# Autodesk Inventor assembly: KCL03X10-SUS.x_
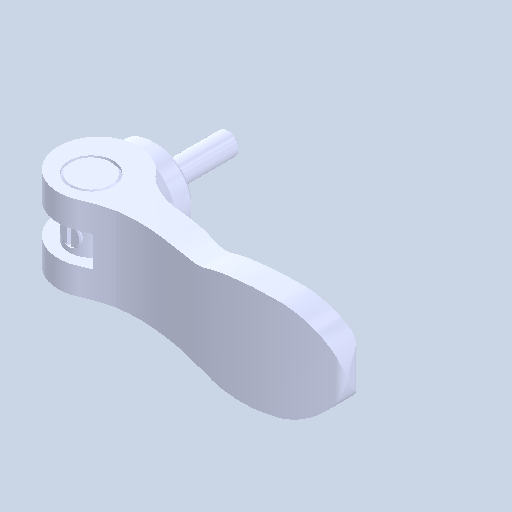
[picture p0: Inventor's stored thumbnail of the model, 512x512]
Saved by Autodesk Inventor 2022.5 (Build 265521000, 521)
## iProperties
Created: 2024-08
Part Number: KCL03X10-SUS.x_
Document SubType Name: Assembly
Designer: ImaoCorp
Author: ImaoCorp
Sending System: SOLIDWORKS 2022-2022290
MC: AMD64
MC_MODEL: Intel64 Family 6 Model 60 Stepping 3, GenuineIntel
OS: Windows_NT
FRU: Parasolid Version 33.1, build 260,  4-25-2022
FORMAT: text
GUISE: transmit
KEY: FILEKCL03X10-SUS.x_t
DATE: Thu Aug 29 10:46:44 2024
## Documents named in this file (5)
- Y:\5.更新分\2024年対応\1001_KCL\データ\kcl03x10-sus\KCL03X10-SUS.x_.iam
- Y:\5.更新分\2024年対応\1001_KCL\データ\kcl03x10-sus\KCL03X10-SUS_01.ipt
- Y:\5.更新分\2024年対応\1001_KCL\データ\kcl03x10-sus\KCL03X10-SUS_02.ipt
- Y:\5.更新分\2024年対応\1001_KCL\データ\kcl03x10-sus\KCL03X10-SUS_03.ipt
- Y:\5.更新分\2024年対応\1001_KCL\データ\kcl03x10-sus\KCL03X10-SUS_04.ipt
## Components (4 placed, 4 different names)
1. KCL03X10-SUS_01
2. KCL03X10-SUS_02
3. KCL03X10-SUS_03
4. KCL03X10-SUS_04
